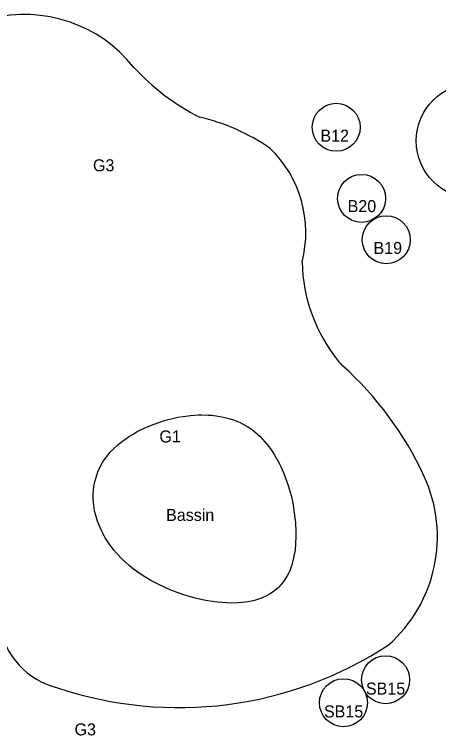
# Model space of a CAD drawing. Extents: x 0 to 512122, y 0 to 6212554.
# Drawn here: x 511760.2 to 511804.4, y 6211690.4 to 6211765.4 of the extents above; entities that cross this region are included whole.
import ezdxf

# ---------------------------------------------------------------- set-up
doc = ezdxf.new("R2010")
doc.units = 0
for name, color, linetype in [('_eks bevares træer', 7, 'Continuous'), ('Bassin - bottom', 7, 'Continuous'), ('TV_U_AFM_Symbl_Gul', 7, 'Continuous'), ('TV_U_LYS_Mastenummer', 7, 'Continuous'), ('TV_U_LYS_Nyx330-Trafiksti-x2', 7, 'Continuous')]:
    doc.layers.add(name, color=color, linetype=linetype)

msp = doc.modelspace()

# ---------------------------------------------------------------- linework, layer by layer
at = {"layer": '_eks bevares træer'}
msp.add_circle((511808.082, 6211752.272), 6, dxfattribs=at)
msp.add_circle((511808.082, 6211752.272), 6, dxfattribs=at)
at = {"layer": 'Bassin - bottom'}
msp.add_lwpolyline([(511770.432, 6211709.854), (511770.154, 6211710.228), (511769.957, 6211710.515), (511769.682, 6211710.954), (511769.316, 6211711.632), (511769.009, 6211712.329), (511768.878, 6211712.683), (511768.665, 6211713.401), (511768.583, 6211713.763), (511768.492, 6211714.309), (511768.433, 6211715.04), (511768.43, 6211715.405), (511768.462, 6211715.952), (511768.538, 6211716.495), (511768.592, 6211716.764), (511768.793, 6211717.475), (511768.925, 6211717.826), (511769.163, 6211718.343), (511769.45, 6211718.848), (511769.613, 6211719.096), (511769.976, 6211719.582), (511770.178, 6211719.819), (511770.505, 6211720.166), (511770.988, 6211720.613), (511771.338, 6211720.9), (511772.099, 6211721.445), (511772.647, 6211721.783), (511773.028, 6211721.997), (511773.826, 6211722.395), (511774.77, 6211722.789), (511775.753, 6211723.123), (511776.257, 6211723.265), (511777.279, 6211723.498), (511777.795, 6211723.586), (511778.572, 6211723.682), (511779.349, 6211723.732), (511779.735, 6211723.739), (511780.417, 6211723.722), (511780.755, 6211723.698), (511781.256, 6211723.642), (511781.993, 6211723.513), (511782.709, 6211723.329), (511783.057, 6211723.214), (511783.732, 6211722.941), (511784.058, 6211722.781), (511784.529, 6211722.511), (511784.979, 6211722.205), (511785.267, 6211721.982), (511785.815, 6211721.493), (511786.074, 6211721.228), (511786.564, 6211720.661), (511787.015, 6211720.05), (511787.296, 6211719.62), (511787.806, 6211718.714), (511787.98, 6211718.361), (511788.301, 6211717.635), (511788.585, 6211716.888), (511788.753, 6211716.382), (511789.041, 6211715.355), (511789.215, 6211714.579), (511789.31, 6211714.062), (511789.453, 6211713.035), (511789.501, 6211712.529), (511789.548, 6211711.538), (511789.549, 6211711.11), (511789.513, 6211710.282), (511789.454, 6211709.69), (511789.314, 6211708.857), (511789.208, 6211708.422), (511789.127, 6211708.145), (511788.94, 6211707.624), (511788.834, 6211707.379), (511788.6, 6211706.919), (511788.335, 6211706.5), (511788.143, 6211706.241), (511787.722, 6211705.775), (511787.552, 6211705.617), (511787.193, 6211705.328), (511786.811, 6211705.073), (511786.542, 6211704.922), (511785.978, 6211704.664), (511785.53, 6211704.507), (511785.221, 6211704.419), (511784.579, 6211704.283), (511784.247, 6211704.233), (511783.563, 6211704.17), (511782.854, 6211704.153), (511782.369, 6211704.166), (511781.374, 6211704.246), (511780.352, 6211704.394), (511779.833, 6211704.493), (511779.051, 6211704.672), (511777.873, 6211705.01), (511776.703, 6211705.428), (511776.126, 6211705.667), (511774.997, 6211706.204), (511774.448, 6211706.501), (511773.649, 6211706.984), (511772.968, 6211707.448), (511772.64, 6211707.693), (511772.163, 6211708.075), (511771.488, 6211708.683), (511770.867, 6211709.332), (511770.578, 6211709.672)], close=True, dxfattribs=at)
at = {"layer": 'TV_U_LYS_Mastenummer'}
for centre in [(511793.746, 6211753.682), (511793.746, 6211753.682), (511796.389, 6211746.282), (511796.389, 6211746.282), (511798.96, 6211741.982), (511798.96, 6211741.982), (511798.889, 6211696.163), (511798.889, 6211696.163), (511794.503, 6211693.773), (511794.503, 6211693.773)]:
    msp.add_circle(centre, 2.5, dxfattribs=at)
at = {"layer": 'TV_U_LYS_Nyx330-Trafiksti-x2'}
for centre, radius, start, end in [((511761.251, 6211750.887), 14.549, 38.49833, 103.97179), ((511790.856, 6211776.823), 24.836, 222.81275, 242.78415), ((511774.915, 6211734.394), 20.852, 55.09781, 77.30409), ((511778.456, 6211742.738), 12.128, 345.32033, 46.22713), ((511807.347, 6211740.083), 17.164, 181.39794, 218.90984), ((511796.735, 6211731.517), 3.527, 218.90984, 228.12058), ((511770.714, 6211702.495), 35.453, 24.73514, 48.12058), ((511789.295, 6211711.055), 14.995, 311.2197, 24.73514), ((511766.63, 6211703.16), 8.067, 189.47836, 256.11817), ((511777.354, 6211733.078), 39.815, 251.46126, 303.2361)]:
    msp.add_arc(centre, radius, start, end, dxfattribs=at)

# ---------------------------------------------------------------- texts
at = {"layer": 'TV_U_AFM_Symbl_Gul'}
for s, p in [('B12', (511792.101, 6211752.186)), ('G3', (511768.405, 6211749.103)), ('B20', (511794.939, 6211744.854)), ('B19', (511797.631, 6211740.497)), ('G1', (511775.325, 6211720.869)), ('Bassin', (511776.026, 6211712.701)), ('SB15', (511796.842, 6211694.623)), ('SB15', (511792.47, 6211692.242)), ('G3', (511766.491, 6211690.368))]:
    msp.add_text(s, height=1.25, dxfattribs=at).set_placement(p)

doc.saveas('drawing.dxf')
